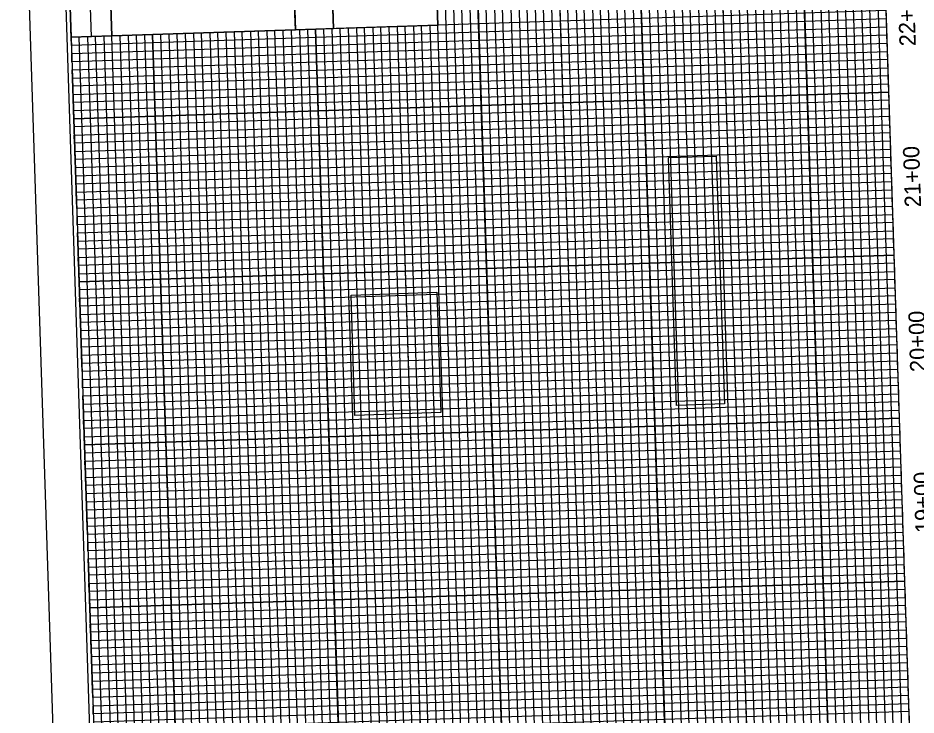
# Model space of a CAD drawing. Extents: x 1627314 to 1628469, y 762309 to 764212.
# Drawn here: x 1627314 to 1627865, y 763361 to 763788 of the extents above; entities that cross this region are included whole.
import ezdxf

# ---------------------------------------------------------------- set-up
doc = ezdxf.new("R2010")
doc.units = 0
for name, color, linetype in [('Exist Vertical Profile Horizontal Axis Label Major', 7, 'Continuous'), ('Old_Level_58', 7, 'Continuous'), ('Prop Grid Mask', 7, 'Continuous'), ('Sheet DOT Grid CELL', 7, 'Continuous'), ('Sheet Layout Profile Border Port 1', 7, 'Continuous'), ('Sheet Plot Border Inside CELL', 7, 'Continuous'), ('Sheet Plot Border Outside CELL', 7, 'Continuous'), ('Sheet Profile CELL', 7, 'Continuous'), ('Sheet Profile Grid Major CELL', 7, 'Continuous'), ('Sheet Profile Grid Middle CELL', 7, 'Continuous'), ('Sheet Profile Grid Minor CELL', 7, 'Continuous'), ('Sheet Sticker Exception Certification CELL', 7, 'Continuous')]:
    doc.layers.add(name, color=color, linetype=linetype)

msp = doc.modelspace()

# ---------------------------------------------------------------- linework, layer by layer
at = {"layer": 'Old_Level_58'}
msp.add_lwpolyline([(1627507.79, 763781.55), (1627501.25, 763981.49), (1627565.16, 763983.58), (1627571.7, 763783.64)], close=True, dxfattribs=at)
at = {"layer": 'Prop Grid Mask'}
for points in [[(1627718.07, 763550.61), (1627713.1, 763702.55), (1627742.38, 763703.51), (1627747.35, 763551.57)], [(1627520.86, 763544.5), (1627518.45, 763618.33), (1627571.15, 763620.05), (1627573.57, 763546.22)]]:
    msp.add_lwpolyline(points, close=True, dxfattribs=at)
at = {"layer": 'Sheet DOT Grid CELL'}
for p, q in [((1627740.07, 763989.32), (1627789.11, 762490.12)), ((1627790.04, 763990.95), (1627839.08, 762491.75)), ((1627590.15, 763984.41), (1627639.19, 762485.21)), ((1627640.12, 763986.05), (1627689.16, 762486.85)), ((1627690.1, 763987.68), (1627739.13, 762488.48)), ((1627846.55, 763792.69), (1627484.3, 763780.84)), ((1627496.74, 763781.25), (1627539.24, 762481.95)), ((1627546.72, 763782.83), (1627589.21, 762483.58)), ((1627396.8, 763777.93), (1627439.29, 762478.68)), ((1627446.77, 763779.57), (1627489.27, 762480.31)), ((1627848.19, 763742.72), (1627348.46, 763726.37)), ((1627849.82, 763692.75), (1627350.09, 763676.4)), ((1627851.46, 763642.77), (1627351.73, 763626.43)), ((1627853.09, 763592.8), (1627353.36, 763576.45)), ((1627854.73, 763542.83), (1627354.99, 763526.48)), ((1627856.36, 763492.85), (1627356.63, 763476.51)), ((1627858, 763442.88), (1627358.26, 763426.53)), ((1627859.63, 763392.91), (1627359.9, 763376.56))]:
    msp.add_line(p, q, dxfattribs=at)
at = {"layer": 'Sheet Layout Profile Border Port 1'}
msp.add_lwpolyline([(1627386.05, 762576.99), (1627885.78, 762593.33), (1627841.65, 763942.61), (1627566.8, 763933.62), (1627570.07, 763833.63), (1627345.19, 763826.32)], close=True, dxfattribs=at)
msp.add_lwpolyline([(1627548.65, 762532.28), (1627887.42, 762543.36), (1627841.65, 763942.61), (1627566.8, 763933.62)], dxfattribs=at)
at = {"layer": 'Sheet Plot Border Inside CELL'}
msp.add_lwpolyline([(1628446.34, 762357.53), (1628391.86, 764023.14), (1627337.33, 763988.65), (1627391.81, 762323.04)], close=True, dxfattribs=at)
at = {"layer": 'Sheet Plot Border Outside CELL'}
msp.add_lwpolyline([(1628469.21, 762345.27), (1628413.63, 764044.37), (1627314.22, 764008.4), (1627369.79, 762309.31)], close=True, dxfattribs=at)
at = {"layer": 'Sheet Profile CELL'}
for p, q in [((1627889.05, 762493.39), (1627840.02, 763992.59)), ((1627359.37, 763776.71), (1627352.83, 763976.65))]:
    msp.add_line(p, q, dxfattribs=at)
for points in [[(1627340.28, 763976.24), (1627389.32, 762477.04), (1628438.76, 762511.37), (1628389.72, 764010.57)], [(1627346.82, 763776.3), (1627340.28, 763976.24), (1627365.32, 763977.06), (1627371.86, 763777.12)], [(1627371.86, 763777.12), (1627368.59, 763877.11), (1627481.03, 763880.79), (1627484.3, 763780.79)]]:
    msp.add_lwpolyline(points, close=True, dxfattribs=at)
at = {"layer": 'Sheet Profile Grid Major CELL'}
for points in [[(1627740.07, 763989.32), (1627789.11, 762490.12), (1627789.11, 762490.12), (1627839.08, 762491.75), (1627790.04, 763990.95)], [(1627546.71, 763782.88), (1627589.21, 762483.58), (1627639.19, 762485.21), (1627590.15, 763984.41)], [(1627640.12, 763986.05), (1627689.16, 762486.85), (1627739.13, 762488.48), (1627690.1, 763987.68)], [(1627861.27, 763342.93), (1627859.63, 763392.91), (1627359.9, 763376.56), (1627358.26, 763426.53), (1627858, 763442.88), (1627856.36, 763492.85), (1627356.63, 763476.51), (1627354.99, 763526.48), (1627854.73, 763542.83), (1627853.09, 763592.8), (1627353.36, 763576.45), (1627351.73, 763626.43), (1627851.46, 763642.77), (1627849.82, 763692.75), (1627350.09, 763676.4), (1627348.46, 763726.37), (1627848.19, 763742.72), (1627846.55, 763792.69), (1627346.82, 763776.35), (1627345.96, 763802.63)], [(1627446.77, 763779.62), (1627489.27, 762480.31), (1627539.24, 762481.95), (1627496.74, 763781.25)], [(1627439.29, 762478.68), (1627396.79, 763777.98)]]:
    msp.add_lwpolyline(points, dxfattribs=at)
at = {"layer": 'Sheet Profile Grid Middle CELL'}
msp.add_line((1627414.31, 762477.86), (1627371.81, 763777.11), dxfattribs=at)
for points in [[(1627715.08, 763988.5), (1627764.12, 762489.3), (1627814.09, 762490.94), (1627765.06, 763990.13)], [(1627815.03, 763991.77), (1627864.07, 762492.57)], [(1627615.14, 763985.23), (1627664.17, 762486.03), (1627714.15, 762487.67), (1627665.11, 763986.86)], [(1627360.72, 763351.57), (1627860.45, 763367.92), (1627858.81, 763417.89), (1627359.08, 763401.55), (1627357.45, 763451.52), (1627857.18, 763467.87), (1627855.54, 763517.84), (1627355.81, 763501.49), (1627354.18, 763551.47), (1627853.91, 763567.81), (1627852.28, 763617.79), (1627352.54, 763601.44), (1627350.91, 763651.41), (1627850.64, 763667.76), (1627849.01, 763717.73), (1627349.27, 763701.39), (1627347.64, 763751.36), (1627847.37, 763767.71), (1627845.74, 763817.68), (1627570.88, 763808.69)], [(1627521.73, 763782.02), (1627564.23, 762482.76), (1627614.2, 762484.4), (1627570.88, 763808.69)], [(1627421.78, 763778.8), (1627464.28, 762479.49), (1627514.25, 762481.13), (1627471.75, 763780.43)]]:
    msp.add_lwpolyline(points, dxfattribs=at)
at = {"layer": 'Sheet Profile Grid Minor CELL'}
for p, q in [((1627792.47, 762540.25), (1627746.7, 763939.51)), ((1627751.7, 763939.67), (1627797.47, 762540.42)), ((1627802.47, 762540.58), (1627756.7, 763939.83)), ((1627761.69, 763940), (1627807.46, 762540.75)), ((1627817.46, 762541.07), (1627771.69, 763940.32)), ((1627776.69, 763940.49), (1627822.45, 762541.24)), ((1627827.45, 762541.4), (1627781.68, 763940.65)), ((1627786.68, 763940.81), (1627832.45, 762541.56)), ((1627842.44, 762541.89), (1627796.67, 763941.14)), ((1627801.67, 763941.3), (1627847.44, 762542.05)), ((1627852.44, 762542.22), (1627806.67, 763941.47)), ((1627811.67, 763941.63), (1627857.44, 762542.38)), ((1627867.43, 762542.71), (1627821.66, 763941.96)), ((1627826.66, 763942.12), (1627872.43, 762542.87)), ((1627877.42, 762543.03), (1627831.66, 763942.29)), ((1627576.79, 763933.95), (1627622.56, 762534.7)), ((1627627.56, 762534.86), (1627581.79, 763934.11)), ((1627586.79, 763934.28), (1627632.56, 762535.02)), ((1627642.55, 762535.35), (1627596.78, 763934.6)), ((1627601.78, 763934.77), (1627647.55, 762535.51)), ((1627652.55, 762535.68), (1627606.78, 763934.93)), ((1627611.77, 763935.09), (1627657.54, 762535.84)), ((1627667.54, 762536.17), (1627621.77, 763935.42)), ((1627626.77, 763935.58), (1627672.53, 762536.33)), ((1627677.53, 762536.5), (1627631.76, 763935.75)), ((1627636.76, 763935.91), (1627682.53, 762536.66)), ((1627692.52, 762536.99), (1627646.75, 763936.24)), ((1627651.75, 763936.4), (1627697.52, 762537.15)), ((1627702.52, 762537.31), (1627656.75, 763936.56)), ((1627661.75, 763936.73), (1627707.52, 762537.48)), ((1627717.51, 762537.8), (1627671.74, 763937.05)), ((1627676.74, 763937.22), (1627722.51, 762537.97)), ((1627727.51, 762538.13), (1627681.74, 763937.38)), ((1627686.73, 763937.55), (1627732.5, 762538.29)), ((1627742.5, 762538.62), (1627696.73, 763937.87)), ((1627701.73, 763938.04), (1627747.49, 762538.78)), ((1627752.49, 762538.95), (1627706.72, 763938.2)), ((1627711.72, 763938.36), (1627757.49, 762539.11)), ((1627767.48, 762539.44), (1627721.71, 763938.69)), ((1627726.71, 763938.85), (1627772.48, 762539.6)), ((1627731.71, 763939.02), (1627777.48, 762539.76)), ((1627736.71, 763939.18), (1627782.48, 762539.93)), ((1627481.75, 763780.71), (1627522.61, 762531.43)), ((1627486.75, 763780.92), (1627527.61, 762531.59)), ((1627491.74, 763781.09), (1627532.61, 762531.75)), ((1627542.6, 762532.08), (1627501.74, 763781.41)), ((1627506.74, 763781.58), (1627547.6, 762532.25)), ((1627552.6, 762532.41), (1627511.73, 763781.69)), ((1627531.72, 763782.34), (1627572.59, 762533.06)), ((1627577.59, 762533.23), (1627536.72, 763782.51)), ((1627556.71, 763783.16), (1627597.57, 762533.88)), ((1627602.57, 762534.04), (1627561.71, 763783.33)), ((1627392.68, 762527.18), (1627351.82, 763776.51)), ((1627356.82, 763776.67), (1627398.03, 762527.35)), ((1627402.68, 762527.5), (1627361.81, 763776.84))]:
    msp.add_line(p, q, dxfattribs=at)
for points in [[(1627836.65, 763942.45), (1627882.42, 762543.2)], [(1627566.71, 763783.49), (1627607.57, 762534.21), (1627617.56, 762534.53), (1627571.79, 763933.79)], [(1627850.15, 763682.75), (1627849.99, 763687.75), (1627350.25, 763671.4), (1627349.93, 763681.4), (1627849.66, 763697.74), (1627849.5, 763702.74), (1627349.76, 763686.39), (1627349.6, 763691.39), (1627849.33, 763707.74), (1627849.17, 763712.74), (1627349.44, 763696.39), (1627349.11, 763706.38), (1627848.84, 763722.73), (1627848.68, 763727.73), (1627348.95, 763711.38), (1627348.78, 763716.38), (1627848.52, 763732.72), (1627848.35, 763737.72), (1627348.62, 763721.38), (1627348.29, 763731.37), (1627848.03, 763747.72), (1627847.86, 763752.71), (1627348.13, 763736.37), (1627347.97, 763741.37), (1627847.7, 763757.71), (1627847.53, 763762.71), (1627347.8, 763746.36), (1627347.48, 763756.36), (1627847.21, 763772.7), (1627847.04, 763777.7), (1627347.31, 763761.35), (1627347.15, 763766.35), (1627846.88, 763782.7), (1627846.72, 763787.7), (1627346.98, 763771.35), (1627346.66, 763781.34)], [(1627441.77, 763779.45), (1627482.64, 762530.12), (1627492.63, 762530.45), (1627451.77, 763779.78)], [(1627456.86, 763779.95), (1627497.72, 762530.71), (1627502.62, 762530.87), (1627461.76, 763780.11)], [(1627466.76, 763780.27), (1627507.62, 762530.94), (1627517.62, 762531.26), (1627476.75, 763780.6)], [(1627516.73, 763781.85), (1627557.6, 762532.57), (1627567.59, 762532.9), (1627526.73, 763782.18)], [(1627541.72, 763782.67), (1627582.58, 762533.39), (1627592.58, 762533.72), (1627551.71, 763783)], [(1627366.81, 763777), (1627407.68, 762527.67), (1627417.67, 762528), (1627376.81, 763777.33)], [(1627381.8, 763777.44), (1627422.67, 762528.16), (1627427.67, 762528.32), (1627386.8, 763777.65)], [(1627391.8, 763777.82), (1627432.66, 762528.49), (1627442.66, 762528.81), (1627401.79, 763778.14)], [(1627406.79, 763778.31), (1627447.65, 762528.98), (1627452.65, 762529.14), (1627411.79, 763778.47)], [(1627416.78, 763778.63), (1627457.65, 762529.3), (1627467.64, 762529.63), (1627426.78, 763778.96)], [(1627431.78, 763779.13), (1627472.64, 762529.79), (1627477.64, 762529.96), (1627436.77, 763779.29)], [(1627860.12, 763377.91), (1627360.39, 763361.57), (1627360.23, 763366.57), (1627859.96, 763382.91), (1627859.79, 763387.91), (1627360.06, 763371.56), (1627359.73, 763381.56), (1627859.47, 763397.9), (1627859.3, 763402.9), (1627359.57, 763386.55), (1627359.41, 763391.55), (1627859.14, 763407.9), (1627858.98, 763412.9), (1627359.24, 763396.55), (1627358.92, 763406.54), (1627858.65, 763422.89), (1627858.49, 763427.89), (1627358.75, 763411.54), (1627358.59, 763416.54), (1627858.32, 763432.88), (1627858.16, 763437.88), (1627358.43, 763421.54), (1627358.1, 763431.53), (1627857.83, 763447.88), (1627857.67, 763452.87), (1627357.94, 763436.53), (1627357.77, 763441.53), (1627857.51, 763457.87), (1627857.34, 763462.87), (1627357.61, 763446.52), (1627357.28, 763456.52), (1627857.02, 763472.86), (1627856.85, 763477.86), (1627357.12, 763461.51), (1627356.96, 763466.51), (1627856.69, 763482.86), (1627856.53, 763487.86), (1627356.79, 763471.51), (1627356.47, 763481.5), (1627856.2, 763497.85), (1627856.03, 763502.85), (1627356.3, 763486.5), (1627356.14, 763491.5), (1627855.87, 763507.84), (1627855.71, 763512.84), (1627355.98, 763496.5), (1627355.65, 763506.49), (1627855.38, 763522.84), (1627855.22, 763527.83), (1627355.48, 763511.49), (1627355.32, 763516.49), (1627855.05, 763532.83), (1627854.89, 763537.83), (1627355.16, 763521.48), (1627354.83, 763531.48), (1627854.56, 763547.82), (1627854.4, 763552.82), (1627354.67, 763536.47), (1627354.5, 763541.47), (1627854.24, 763557.82), (1627854.07, 763562.82), (1627354.34, 763546.47), (1627354.01, 763556.46), (1627853.75, 763572.81), (1627853.58, 763577.81), (1627353.85, 763561.46), (1627353.69, 763566.46), (1627853.42, 763582.8), (1627853.26, 763587.8), (1627353.52, 763571.46), (1627353.2, 763581.45), (1627852.93, 763597.8), (1627852.77, 763602.79), (1627353.03, 763586.45), (1627352.87, 763591.45), (1627852.6, 763607.79), (1627852.44, 763612.79), (1627352.71, 763596.44), (1627352.38, 763606.44), (1627852.11, 763622.78), (1627851.95, 763627.78), (1627352.22, 763611.43), (1627352.05, 763616.43), (1627851.78, 763632.78), (1627851.62, 763637.78), (1627351.89, 763621.43), (1627351.56, 763631.42), (1627851.29, 763647.77), (1627851.13, 763652.77), (1627351.4, 763636.42), (1627351.23, 763641.42), (1627850.97, 763657.76), (1627850.8, 763662.76), (1627351.07, 763646.42), (1627350.74, 763656.41), (1627850.48, 763672.76), (1627850.31, 763677.75), (1627350.58, 763661.41), (1627350.42, 763666.41), (1627850.15, 763682.75)], [(1627360.55, 763356.57), (1627860.28, 763372.92), (1627860.12, 763377.91)], [(1627860.78, 763357.93), (1627860.61, 763362.92), (1627360.88, 763346.58)]]:
    msp.add_lwpolyline(points, dxfattribs=at)
at = {"layer": 'Sheet Sticker Exception Certification CELL'}
for p, q in [((1627484.3, 763780.79), (1627477.76, 763980.72)), ((1627484.3, 763780.79), (1627477.76, 763980.72)), ((1627501.25, 763981.49), (1627507.79, 763781.56)), ((1627501.25, 763981.49), (1627507.79, 763781.56)), ((1627507.79, 763781.56), (1627484.3, 763780.79)), ((1627507.79, 763781.56), (1627484.3, 763780.79))]:
    msp.add_line(p, q, dxfattribs=at)

# ---------------------------------------------------------------- texts
at = {"layer": 'Exist Vertical Profile Horizontal Axis Label Major'}
for s, p in [('22+00', (1627864.77, 763771.05)), ('21+00', (1627868, 763672.32)), ('20+00', (1627871.3, 763571.32)), ('19+00', (1627874.53, 763472.61))]:
    msp.add_text(s, height=10, rotation=91.8735, dxfattribs=at).set_placement(p)

doc.saveas('drawing.dxf')
